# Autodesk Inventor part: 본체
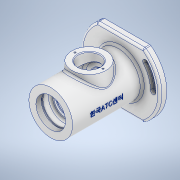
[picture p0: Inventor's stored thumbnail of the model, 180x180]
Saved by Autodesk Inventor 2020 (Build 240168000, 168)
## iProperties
Created: 2022-05
Part Number: 본체
Material: 알루미늄 6061
Document SubType Name: Modeling
Designer: Student
Density: 2.7 g/cm^3
Appearance: 알루미늄 - 평지
Mass: 694.374 g
Surface Area: 622.592 cm^2
Volume: 257.175 cm^3
Author: Student
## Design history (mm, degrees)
sketch "스케치1"
  geometry: L1 (0, 57.5)-(0, -57.5); L2 (32, 57.5)-(32, -44.5); L3 (32, -44.5)-(58, -44.5); L4 (58, -44.5)-(58, -54.5); L5 (58, -54.5)-(36, -54.5); L6 (36, -54.5)-(36, -57.5); L7 (36, -57.5)-(30, -57.5); L8 (30, -57.5)-(20, -43.5); L9 (14.596, -36.2)-(11, -36.2); L10 (11, -36.2)-(11, -33.5); L11 (11, -33.5)-(15, -33.5); L12 (15, -33.5)-(15, -28.5); L13 (15, -28.5)-(17.5, -28.5); L14 (17.5, -28.5)-(17.5, -17.5); L15 (17.5, -17.5)-(27, -17.5); L16 (27, -17.5)-(27, 20.5); L17 (27, 20.5)-(17.5, 20.5); L18 (17.5, 20.5)-(17.5, 31.5); L19 (17.5, 31.5)-(18.5, 31.5); L20 (18.5, 31.5)-(18.5, 33.25); L21 (18.5, 33.25)-(17.5, 33.25); L22 (17.5, 33.25)-(17.5, 35.5); L23 (17.5, 35.5)-(22.5, 35.5); L24 (22.5, 35.5)-(22.5, 46.5); L25 (22.5, 46.5)-(24, 46.5); L26 (24, 46.5)-(24, 49.5); L27 (24, 49.5)-(0, 49.5); L28 (32, 57.5)-(0, 57.5); L29 (14.596, -36.2)-(14.596, -42.8); L30 (14.596, -42.8)-(15, -43.5); L31 (15, -43.5)-(20, -43.5); 3 further points
  constraints: 62 end point, 21 perpendicular, 4 vertical, 2 horizontal, 2 midpoint, 2 point on line, 1 coincident, 1 horizontal alignment
  dimensions: "d0" = 115 distance of L1.start L1.end; "d1" = 64 diameter of L2 L1; "d2" = 116 diameter of L4 L1; "d3" = 72 diameter of L6 L1; "d4" = 60 diameter of L7.end L1; "d5" = 40 diameter of L8.end L1; "d6" = 22 diameter of L10 L1; "d9" = 150 deg angle of L29 L30; "d10" = 0.7 distance from line of L29.end L31; "d11" = 30 diameter of L30.end L1; "d12" = 14 distance between parallel lines of L31 L7; "d13" = 6.6 distance of L9.start L29.end; "d15" = 5 distance from line of L12.end L11; "d16" = 29 distance between parallel lines of L7 L13; "d17" = 11 distance from line of L14.end L13; "d18" = 38 distance from line of L16.end L15; "d19" = 54 diameter of L16 L1; "d20" = 30 diameter of L12 L1; "d21" = 35 diameter of L14 L1; "d22" = 35 diameter of L18 L1; "d23" = 37 diameter of L20 L1; "d24" = 11 distance between parallel lines of L19 L17; "d25" = 1.75 distance between parallel lines of L21 L19; "d26" = 4 distance between parallel lines of L23 L19; "d27" = 45 diameter of L24 L1; "d28" = 22 distance between parallel lines of L28 L23; "d29" = 3 distance between parallel lines of L27 L25; "d30" = 8 distance between parallel lines of L28 L27; "d31" = 48 diameter of L26 L1; "d32" = 13 distance between parallel lines of L3 L7; "d33" = 3 distance between parallel lines of L7 L5
revolve "회전1" sketch "스케치1" stored, may be unused: angle "d34" = 90 deg
sketch "스케치2"
  geometry: C1 r 11 at (0, 0) reference; 2 further points
  constraints: 1 coincident
hole "구멍1" sketch "스케치2" at (0, 0) diameter "d35" = 43.376; stored, may be unused: countersink angle "d39" = 90 deg, drill point angle "d41" = 0 deg; dims "d36" = 8, "d37" = 4, "d38" = 2, "d40" = 10
sketch "스케치3"
  geometry: L1 (-33.985, 47)-(33.985, 47); L2 (33.985, -47)-(-33.985, -47); L3 (0, 47)-(0, -47); A1 r 58 centre (0, 0) between (-33.985, 47) and (33.985, 47) reference; 2 further points
  constraints: 6 end point, 4 point on circle, 3 midpoint, 1 coincident, 1 horizontal, 1 parallel
  dimensions: "d42" = 94 distance between parallel lines of L2 L1
extrude "돌출1" cut sketch "스케치3" distance "d43" = 10; taper "d44" = 0 deg
sketch "스케치4"
  geometry: L1 (33.985, 47)-(-2.785, 16.146); L2 (33.985, 47)-(-14.015, 47); L3 (33.985, 47)-(70.755, 77.854); L4 (33.985, 47)-(81.985, 47); A1 r 48 centre (33.985, 47) between (-14.015, 47) and (-2.785, 16.146); A2 r 52 centre (33.985, 47) between (-18.015, 47) and (-5.849, 13.575); A3 r 44 centre (33.985, 47) between (-10.015, 47) and (0.279, 18.717); A4 r 4 centre (-14.015, 47) between (-10.015, 47) and (-18.015, 47); A5 r 4 centre (-2.785, 16.146) between (-5.849, 13.575) and (0.279, 18.717); A6 r 48 centre (33.985, 47) between (81.985, 47) and (70.755, 77.854); A7 r 52 centre (33.985, 47) between (85.985, 47) and (73.82, 80.425); A8 r 44 centre (33.985, 47) between (77.985, 47) and (67.691, 75.283); A9 r 4 centre (81.985, 47) between (77.985, 47) and (85.985, 47); A10 r 4 centre (70.755, 77.854) between (73.82, 80.425) and (67.691, 75.283); 2 further points
  constraints: 20 point on circle, 10 centre point, 8 end point, 8 tangent, 2 coincident, 1 horizontal, 1 point on line
  dimensions: "d47" = 48 radius of A1; "d48" = 40 deg angle of L2 L1; "d50" = 4 radius of A4; "d51" = 40 deg angle of L4 L3; "d52" = 4 radius of A10; "d53" = 48 radius of A6
extrude "돌출2" cut sketch "스케치4" distance "d54" = 4.4; taper "d55" = 0 deg
sketch "스케치5"
  geometry: L1 (33.985, 47)-(70.755, 77.854); L2 (33.985, 47)-(81.985, 47); L3 (33.985, 47)-(-2.785, 16.146); L4 (33.985, 47)-(-14.015, 47); C1 r 15 at (33.985, 47) reference; A1 r 48 centre (33.985, 47) between (81.985, 47) and (70.755, 77.854); A2 r 50.25 centre (33.985, 47) between (84.235, 47) and (72.479, 79.3); A3 r 45.75 centre (33.985, 47) between (79.735, 47) and (69.032, 76.408); A4 r 2.25 centre (81.985, 47) between (79.735, 47) and (84.235, 47); A5 r 2.25 centre (70.755, 77.854) between (72.479, 79.3) and (69.032, 76.408); A6 r 48 centre (33.985, 47) between (-14.015, 47) and (-2.785, 16.146); A7 r 50.25 centre (33.985, 47) between (-16.265, 47) and (-4.508, 14.7); A8 r 45.75 centre (33.985, 47) between (-11.765, 47) and (-1.061, 17.592); A9 r 2.25 centre (-14.015, 47) between (-11.765, 47) and (-16.265, 47); A10 r 2.25 centre (-2.785, 16.146) between (-4.508, 14.7) and (-1.061, 17.592); 1 further point
  constraints: 21 point on circle, 10 centre point, 8 end point, 8 tangent, 2 coincident, 1 horizontal
  dimensions: "d56" = 48 radius of A1; "d57" = 40 deg angle of L2 L1; "d58" = 2.25 radius of A5; "d59" = 40 deg angle of L4 L3; "d60" = 2.25 radius of A10; "d61" = 140 deg angle of L2 L3
extrude "돌출3" cut sketch "스케치5" distance "d62" = 5.6; taper "d63" = 0 deg
sketch "스케치6"
  geometry: C1 r 4 at (70.755, 77.854); C2 r 4 at (-2.785, 16.146); A1 r 4 centre (70.755, 77.854) between (73.82, 80.425) and (67.691, 75.283) reference; A2 r 4 centre (-14.015, 47) between (-10.015, 47) and (-18.015, 47) reference; A3 r 2.25 centre (-2.785, 16.146) between (-4.508, 14.7) and (-1.061, 17.592) reference; 3 further points
  constraints: 2 centre point, 2 coincident
extrude "돌출4" cut sketch "스케치6" distance "d64" = 5.6; taper "d65" = 0 deg
node "작업 평면1"
sketch "스케치7"
  geometry: L1 (-32, 57.5)-(32, 57.5) reference; C1 r 25 at (0, 1.5); 1 further point
  constraints: 1 centre point
  dimensions: "d67" = 25 radius of C1; "d68" = 56 distance from line of C1.centre L1
extrude "돌출5" join sketch "스케치7" stored distance "d69" = 5.6; taper "d70" = 5 deg; dims "d0" = 115, "d1" = 64, "d2" = 116, "d3" = 72, "d4" = 60, "d5" = 40, "d6" = 22, "d9" = 150 deg, "d10" = 0.7, "d11" = 30, "d12" = 14, "d13" = 6.6, "d15" = 5, "d16" = 29, "d17" = 11, "d18" = 38, "d19" = 54, "d20" = 30, "d21" = 35, "d22" = 35, "d23" = 37, "d24" = 11, "d25" = 1.75, "d26" = 4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
sketch "스케치8"
  geometry: C1 r 25 at (0, 0) reference; C2 r 16 at (0, 0); 1 further point
  constraints: 1 centre point, 1 coincident
  dimensions: "d71" = 16 radius of C2
extrude "돌출6" cut sketch "스케치8" stored distance "d72" = 5.6; taper "d73" = 0 deg
sketch "스케치9"
  geometry: L1 (27, 19)-(-27, 19) reference; L2 (27, -19)-(-27, -19) reference; C1 r 25 at (0, 0) reference; 3 further points
  constraints: 1 other
  dimensions: "d74" = 20.5 distance of C1.centre point (20.5, -0.011)
hole "구멍2" sketch "스케치9" at (20.5, -0.011) diameter "d75" = 2.459; stored, may be unused: countersink angle "d79" = 90 deg, drill point angle "d81" = 118 deg; dims "d76" = 6, "d77" = 4, "d78" = 2, "d80" = 8
node "작업 평면2"
sketch "스케치10"
  geometry: L1 (8.299, 44.594)-(8.299, -29.594); L2 (8.299, -29.594)-(-8.299, -29.594); L3 (-8.299, -29.594)-(-8.299, 44.594); L4 (-8.299, 44.594)-(8.299, 44.594); L5 (-8.299, 44.594)-(8.299, -29.594); L6 (-32, 57.5)-(32, 57.5) reference; L7 (-47, -54.5)-(47, -54.5) reference; L8 (-32, 57.5)-(-32, -44.5) reference; 2 further points
  constraints: 2 end point, 1 midpoint, 2 other
  dimensions: "d87" = 62 distance from line of L7 point (0, 7.5); "d88" = 32 distance from line of L8 point (0, 7.5)
feature "엠보싱1" sketch "스케치10" dims "d0" = 115, "d1" = 64, "d2" = 116, "d3" = 72, "d4" = 60, "d5" = 40, "d6" = 22, "d9" = 150 deg, "d10" = 0.7, "d11" = 30, "d12" = 14, "d13" = 6.6, "d15" = 5, "d16" = 29, "d17" = 11, "d18" = 38, "d19" = 54, "d20" = 30, "d21" = 35, "d22" = 35, "d23" = 37, "d24" = 11, "d25" = 1.75, "d26" = 4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
fillet "모깎기1" dims "d91" = 3
fillet "모깎기2" dims "d92" = 3
fillet "모깎기3" dims "d93" = 3
chamfer "모따기1" distance "d94" = 1; stored, may be unused: second distance "d95" = 2, angle "d96" = 45 deg
fillet "모깎기4" dims "d97" = 3
chamfer "모따기2" distance "d98" = 1; stored, may be unused: second distance "d99" = 2, angle "d100" = 45 deg
fillet "모깎기5" dims "d101" = 3
fillet "모깎기6" dims "d102" = 0.6
fillet "모깎기7" dims "d103" = 3
fillet "모깎기8" dims "d104" = 0.5
node "솔리드1"
pattern_circular "원형 패턴1" dims angle "d83" = 360 deg
node "투영된 루프1"
feature "A9D066F2-1C7D-4E18-AEED-F7BC21143FA4" dims "d35" = 43.376, "d36" = 8, "d37" = 4, "d38" = 2, "d39" = 90 deg, "d40" = 10, "d41" = 0
other parameters: "d66" = 38, "d85" = 32.5
